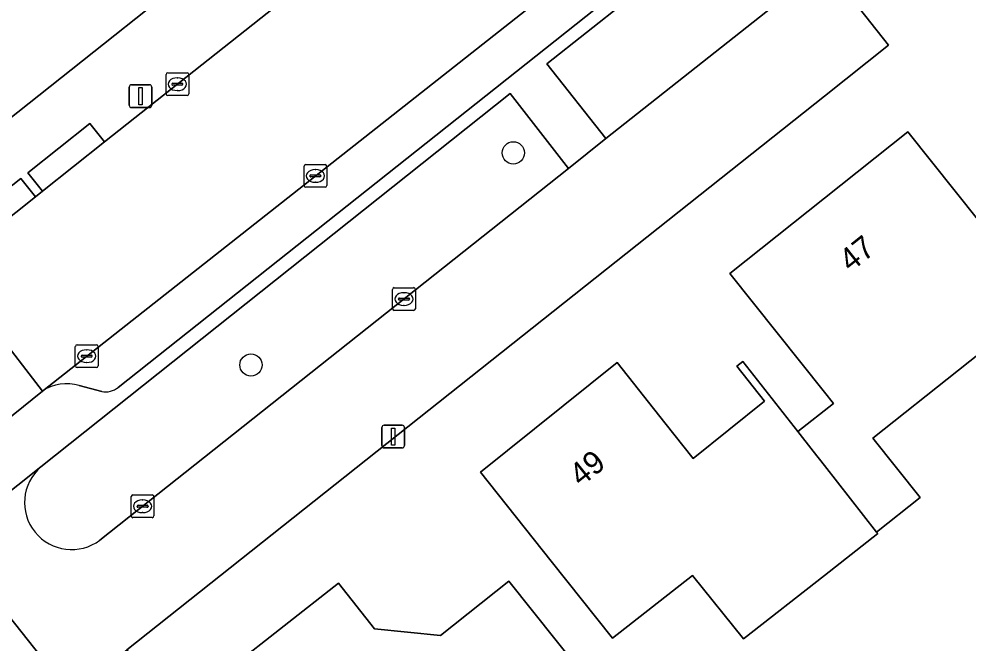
# Model space of a CAD drawing. Extents: x 159499 to 160349, y 382524 to 383273.
# Drawn here: x 159964.6 to 160006.36, y 383112.66 to 383140.09 of the extents above; entities that cross this region are included whole.
import ezdxf

# ---------------------------------------------------------------- set-up
doc = ezdxf.new("R2010")
doc.units = 0
for name, color, linetype in [('IMGEO_Boom', 7, 'Continuous'), ('IMGEO_Erf', 7, 'Continuous'), ('IMGEO_Groenvoorziening', 7, 'Continuous'), ('IMGEO_Kolk', 7, 'Continuous'), ('IMGEO_Lichtmast', 7, 'Continuous'), ('IMGEO_Pand', 7, 'Continuous'), ('IMGEO_Pand_nummerreeks', 7, 'Continuous'), ('IMGEO_Parkeervlak_open', 7, 'Continuous'), ('IMGEO_Rijbaan_lokaal_open', 7, 'Continuous'), ('IMGEO_Voetpad_open', 7, 'Continuous')]:
    doc.layers.add(name, color=color, linetype=linetype)

msp = doc.modelspace()

# ---------------------------------------------------------------- linework, layer by layer
at = {"layer": 'IMGEO_Boom'}
for centre in [(159986.328, 383134.208), (159974.796, 383124.886)]:
    msp.add_circle(centre, 0.489, dxfattribs=at)
at = {"layer": 'IMGEO_Erf'}
for points in [[(159838.776, 383036.162), (160000, 383164.155)], [(160069.07, 383073.156), (160071.919, 383076.914), (160077.006, 383081.993), (160081.991, 383086.829), (160067.75, 383101.08), (160016.301, 383152.744), (160001.274, 383140.9), (160002.826, 383138.938), (160000, 383136.696), (159969.339, 383112.369), (160000, 383073.962), (160006.879, 383065.344), (160051.214, 383033.728), (160053.92, 383031.798), (160060.452, 383040.944)]]:
    msp.add_lwpolyline(points, dxfattribs=at)
for points in [[(160004.209, 383119.058), (160002.296, 383117.538), (160002.349, 383117.471), (160000, 383115.631), (159996.451, 383112.851), (159994.2, 383115.629), (159990.696, 383112.874), (159987.999, 383116.264), (159984.887, 383120.176), (159990.894, 383124.991), (159992.99, 383122.344), (159994.232, 383120.776), (159997.365, 383123.295), (159996.151, 383124.828), (159996.416, 383125.034), (159998.829, 383121.957), (160000.398, 383123.188), (160000, 383123.688), (159995.843, 383128.911), (160000, 383132.215), (160003.671, 383135.132), (160006.794, 383131.227), (160009.659, 383127.643), (160002.137, 383121.666)], [(159990.718, 383109.639), (159985.126, 383105.184), (159985.737, 383104.418), (159986.361, 383104.917), (159987.389, 383103.626), (159986.881, 383103.221), (159982.971, 383100.104), (159980.091, 383103.717), (159980.599, 383104.122), (159978.131, 383107.219), (159977.63, 383106.82), (159973.87, 383111.54), (159978.65, 383115.3), (159980.233, 383113.288), (159983.128, 383112.99), (159986.139, 383115.388), (159989.255, 383111.477)]]:
    msp.add_lwpolyline(points, close=True, dxfattribs=at)
at = {"layer": 'IMGEO_Groenvoorziening'}
for points in [[(160009.287, 383155.131), (160000, 383147.78), (159987.796, 383138.118), (159990.398, 383134.835), (160000, 383142.448), (160012.044, 383151.997)], [(159988.759, 383133.521), (159986.191, 383136.82), (159965.56, 383120.401)], [(159968.16, 383117.19), (159988.759, 383133.521)]]:
    msp.add_lwpolyline(points, dxfattribs=at)
msp.add_arc((159966.913, 383118.839), 2.067, 130.8921, 307.1032, dxfattribs=at)
at = {"layer": 'IMGEO_Kolk'}
for p, q in [((159971.064, 383136.801), (159971.064, 383137.653)), ((159971.139, 383137.727), (159971.991, 383137.727)), ((159971.552, 383137.507), (159971.577, 383137.507)), ((159972.065, 383137.653), (159972.065, 383136.801)), ((159971.323, 383137.221), (159971.323, 383137.233)), ((159971.761, 383137.184), (159971.363, 383137.184)), ((159971.366, 383137.27), (159971.764, 383137.27)), ((159971.807, 383137.233), (159971.807, 383137.221)), ((159971.991, 383136.727), (159971.139, 383136.727)), ((159971.575, 383136.947), (159971.55, 383136.947)), ((159977.206, 383133.696), (159978.058, 383133.696)), ((159977.131, 383132.77), (159977.131, 383133.622)), ((159977.433, 383133.239), (159977.831, 383133.239)), ((159977.619, 383133.476), (159977.644, 383133.476)), ((159978.132, 383133.622), (159978.132, 383132.77)), ((159977.39, 383133.19), (159977.39, 383133.202)), ((159977.828, 383133.153), (159977.43, 383133.153)), ((159977.642, 383132.916), (159977.617, 383132.916)), ((159977.874, 383133.202), (159977.874, 383133.19)), ((159978.058, 383132.696), (159977.206, 383132.696)), ((159981.022, 383127.357), (159981.022, 383128.209)), ((159981.097, 383128.283), (159981.949, 383128.283)), ((159982.023, 383128.209), (159982.023, 383127.357)), ((159981.324, 383127.826), (159981.722, 383127.826)), ((159981.51, 383128.063), (159981.535, 383128.063)), ((159981.281, 383127.777), (159981.281, 383127.789)), ((159981.719, 383127.74), (159981.321, 383127.74)), ((159981.533, 383127.503), (159981.508, 383127.503)), ((159981.765, 383127.789), (159981.765, 383127.777)), ((159981.949, 383127.283), (159981.097, 383127.283)), ((159967.153, 383125.773), (159968.005, 383125.773)), ((159967.078, 383124.847), (159967.078, 383125.699)), ((159967.38, 383125.316), (159967.778, 383125.316)), ((159967.566, 383125.553), (159967.591, 383125.553)), ((159968.079, 383125.699), (159968.079, 383124.847)), ((159967.337, 383125.267), (159967.337, 383125.279)), ((159967.775, 383125.23), (159967.377, 383125.23)), ((159967.589, 383124.993), (159967.564, 383124.993)), ((159967.821, 383125.279), (159967.821, 383125.267)), ((159968.005, 383124.773), (159967.153, 383124.773)), ((159969.532, 383118.248), (159969.532, 383119.1)), ((159969.607, 383119.174), (159970.459, 383119.174)), ((159970.533, 383119.1), (159970.533, 383118.248)), ((159969.791, 383118.668), (159969.791, 383118.68)), ((159970.229, 383118.631), (159969.831, 383118.631)), ((159969.834, 383118.717), (159970.232, 383118.717)), ((159970.02, 383118.954), (159970.045, 383118.954)), ((159970.275, 383118.68), (159970.275, 383118.668)), ((159970.043, 383118.394), (159970.018, 383118.394)), ((159970.459, 383118.174), (159969.607, 383118.174))]:
    msp.add_line(p, q, dxfattribs=at)
for points in [[(159971.064, 383136.801), (159971.064, 383137.653)], [(159971.139, 383137.727), (159971.991, 383137.727)], [(159972.065, 383137.653), (159972.065, 383136.801)], [(159971.991, 383136.727), (159971.139, 383136.727)], [(159977.206, 383133.696), (159978.058, 383133.696)], [(159977.131, 383132.77), (159977.131, 383133.622)], [(159978.132, 383133.622), (159978.132, 383132.77)], [(159978.058, 383132.696), (159977.206, 383132.696)], [(159981.022, 383127.357), (159981.022, 383128.209)], [(159981.097, 383128.283), (159981.949, 383128.283)], [(159982.023, 383128.209), (159982.023, 383127.357)], [(159981.949, 383127.283), (159981.097, 383127.283)], [(159967.153, 383125.773), (159968.005, 383125.773)], [(159967.078, 383124.847), (159967.078, 383125.699)], [(159968.079, 383125.699), (159968.079, 383124.847)], [(159968.005, 383124.773), (159967.153, 383124.773)], [(159969.532, 383118.248), (159969.532, 383119.1)], [(159969.607, 383119.174), (159970.459, 383119.174)], [(159970.533, 383119.1), (159970.533, 383118.248)], [(159970.459, 383118.174), (159969.607, 383118.174)]]:
    msp.add_lwpolyline(points, dxfattribs=at)
for centre, radius, start, end in [((159971.141, 383137.651), 0.0765, 91.552, 178.448), ((159971.141, 383137.651), 0.0765, 91.552, 178.448), ((159971.989, 383137.651), 0.0765, 1.552, 88.448), ((159971.989, 383137.651), 0.0765, 1.552, 88.448), ((159971.363, 383137.23), 0.0403, 85.8775, 175.7526), ((159971.36, 383137.22), 0.0366, 178.938, 274.7102), ((159971.764, 383137.227), 0.043, 264.8664, 352.4533), ((159971.768, 383137.232), 0.0386, 1.7309, 96.639), ((159971.141, 383136.803), 0.0765, 181.552, 268.448), ((159971.141, 383136.803), 0.0765, 181.552, 268.448), ((159971.989, 383136.803), 0.0765, 271.552, 358.448), ((159971.989, 383136.803), 0.0765, 271.552, 358.448), ((159977.208, 383133.62), 0.0765, 91.552, 178.448), ((159977.208, 383133.62), 0.0765, 91.552, 178.448), ((159978.056, 383133.62), 0.0765, 1.552, 88.448), ((159978.056, 383133.62), 0.0765, 1.552, 88.448), ((159977.43, 383133.199), 0.0403, 85.8775, 175.7526), ((159977.835, 383133.201), 0.0386, 1.7309, 96.639), ((159977.427, 383133.189), 0.0366, 178.938, 274.7102), ((159977.831, 383133.196), 0.043, 264.8664, 352.4533), ((159977.208, 383132.772), 0.0765, 181.552, 268.448), ((159977.208, 383132.772), 0.0765, 181.552, 268.448), ((159978.056, 383132.772), 0.0765, 271.552, 358.448), ((159978.056, 383132.772), 0.0765, 271.552, 358.448), ((159981.099, 383128.207), 0.0765, 91.552, 178.448), ((159981.099, 383128.207), 0.0765, 91.552, 178.448), ((159981.947, 383128.207), 0.0765, 1.552, 88.448), ((159981.947, 383128.207), 0.0765, 1.552, 88.448), ((159981.321, 383127.786), 0.0403, 85.8775, 175.7526), ((159981.726, 383127.788), 0.0386, 1.7309, 96.639), ((159981.318, 383127.776), 0.0366, 178.938, 274.7102), ((159981.722, 383127.783), 0.043, 264.8664, 352.4533), ((159981.099, 383127.359), 0.0765, 181.552, 268.448), ((159981.099, 383127.359), 0.0765, 181.552, 268.448), ((159981.947, 383127.359), 0.0765, 271.552, 358.448), ((159981.947, 383127.359), 0.0765, 271.552, 358.448), ((159967.155, 383125.697), 0.0765, 91.552, 178.448), ((159967.155, 383125.697), 0.0765, 91.552, 178.448), ((159968.003, 383125.697), 0.0765, 1.552, 88.448), ((159968.003, 383125.697), 0.0765, 1.552, 88.448), ((159967.377, 383125.276), 0.0403, 85.8775, 175.7526), ((159967.782, 383125.278), 0.0386, 1.7309, 96.639), ((159967.374, 383125.266), 0.0366, 178.938, 274.7102), ((159967.778, 383125.273), 0.043, 264.8664, 352.4533), ((159967.155, 383124.849), 0.0765, 181.552, 268.448), ((159967.155, 383124.849), 0.0765, 181.552, 268.448), ((159968.003, 383124.849), 0.0765, 271.552, 358.448), ((159968.003, 383124.849), 0.0765, 271.552, 358.448), ((159969.609, 383119.098), 0.0765, 91.552, 178.448), ((159969.609, 383119.098), 0.0765, 91.552, 178.448), ((159970.457, 383119.098), 0.0765, 1.552, 88.448), ((159970.457, 383119.098), 0.0765, 1.552, 88.448), ((159969.831, 383118.677), 0.0403, 85.8775, 175.7526), ((159969.828, 383118.667), 0.0366, 178.938, 274.7102), ((159970.232, 383118.674), 0.043, 264.8664, 352.4533), ((159970.236, 383118.679), 0.0386, 1.7309, 96.639), ((159969.609, 383118.25), 0.0765, 181.552, 268.448), ((159969.609, 383118.25), 0.0765, 181.552, 268.448), ((159970.457, 383118.25), 0.0765, 271.552, 358.448), ((159970.457, 383118.25), 0.0765, 271.552, 358.448)]:
    msp.add_arc(centre, radius, start, end, dxfattribs=at)
for centre, major_axis, ratio, start_param, end_param in [((159971.551, 383137.227), (-0.387, 0.002), 0.722429, 4.712389, 7.853982), ((159971.576, 383137.227), (-0.39, 0.002), 0.717154, 1.570796, 4.712389), ((159977.618, 383133.196), (-0.387, 0.002), 0.722429, 4.712389, 7.853982), ((159977.643, 383133.196), (-0.39, 0.002), 0.717154, 1.570796, 4.712389), ((159981.509, 383127.783), (-0.387, 0.002), 0.722429, 4.712389, 7.853982), ((159981.534, 383127.783), (-0.39, 0.002), 0.717154, 1.570796, 4.712389), ((159967.565, 383125.273), (-0.387, 0.002), 0.722429, 4.712389, 7.853982), ((159967.59, 383125.273), (-0.39, 0.002), 0.717154, 1.570796, 4.712389), ((159970.019, 383118.674), (-0.387, 0.002), 0.722429, 4.712389, 7.853982), ((159970.044, 383118.674), (-0.39, 0.002), 0.717154, 1.570796, 4.712389)]:
    msp.add_ellipse(centre, major_axis=major_axis, ratio=ratio, start_param=start_param, end_param=end_param, dxfattribs=at)
at = {"layer": 'IMGEO_Lichtmast'}
for p, q in [((159969.45, 383136.3), (159969.45, 383137.1)), ((159969.45, 383137.1), (159969.45, 383136.3)), ((159969.55, 383137.2), (159970.34, 383137.2)), ((159970.34, 383137.2), (159969.55, 383137.2)), ((159970.44, 383137.1), (159970.44, 383136.3)), ((159970.44, 383136.3), (159970.44, 383137.1)), ((159970.34, 383136.2), (159969.55, 383136.2)), ((159969.55, 383136.2), (159970.34, 383136.2)), ((159980.555, 383121.339), (159980.555, 383122.139)), ((159980.555, 383122.139), (159980.555, 383121.339)), ((159980.655, 383122.239), (159981.445, 383122.239)), ((159981.445, 383122.239), (159980.655, 383122.239)), ((159981.545, 383122.139), (159981.545, 383121.339)), ((159981.545, 383121.339), (159981.545, 383122.139)), ((159981.445, 383121.239), (159980.655, 383121.239)), ((159980.655, 383121.239), (159981.445, 383121.239))]:
    msp.add_line(p, q, dxfattribs=at)
for points in [[(159969.87, 383137.075), (159970.02, 383137.075), (159970.02, 383136.325), (159969.87, 383136.325), (159969.87, 383137.075)], [(159980.975, 383122.114), (159981.125, 383122.114), (159981.125, 383121.364), (159980.975, 383121.364), (159980.975, 383122.114)]]:
    msp.add_lwpolyline(points, dxfattribs=at)
for centre, start, end in [((159969.55, 383137.1), 90, 180), ((159969.55, 383137.1), 90, 180), ((159970.34, 383137.1), 0, 90), ((159970.34, 383137.1), 360, 90), ((159969.55, 383136.3), 180, 270), ((159969.55, 383136.3), 180, 270), ((159970.34, 383136.3), 270, 0), ((159970.34, 383136.3), 270, 0), ((159980.655, 383122.139), 90, 180), ((159980.655, 383122.139), 90, 180), ((159981.445, 383122.139), 0, 90), ((159981.445, 383122.139), 360, 90), ((159980.655, 383121.339), 180, 270), ((159980.655, 383121.339), 180, 270), ((159981.445, 383121.339), 270, 0), ((159981.445, 383121.339), 270, 0)]:
    msp.add_arc(centre, 0.1, start, end, dxfattribs=at)
at = {"layer": 'IMGEO_Pand'}
for points in [[(160006.794, 383131.227), (160003.671, 383135.132), (160000, 383132.215), (159995.843, 383128.911), (160000, 383123.688), (160000.398, 383123.188), (159998.829, 383121.957), (159999.502, 383121.1), (160000, 383120.466), (160002.296, 383117.538), (160004.209, 383119.058), (160002.137, 383121.666), (160009.659, 383127.643)], [(160000, 383120.466), (159999.502, 383121.1), (159998.829, 383121.957), (159996.416, 383125.034), (159996.151, 383124.828), (159997.365, 383123.295), (159994.232, 383120.776), (159992.99, 383122.344), (159990.894, 383124.991), (159984.887, 383120.176), (159987.999, 383116.264), (159990.696, 383112.874), (159994.2, 383115.629), (159996.451, 383112.851), (160000, 383115.631), (160002.349, 383117.471), (160002.296, 383117.538)], [(159989.255, 383111.477), (159986.139, 383115.388), (159983.128, 383112.99), (159980.233, 383113.288), (159978.65, 383115.3), (159973.87, 383111.54), (159977.63, 383106.82), (159978.131, 383107.219), (159980.599, 383104.122), (159980.091, 383103.717), (159982.971, 383100.104), (159986.881, 383103.221), (159987.389, 383103.626), (159986.361, 383104.917), (159985.737, 383104.418), (159985.126, 383105.184), (159990.718, 383109.639)]]:
    msp.add_lwpolyline(points, close=True, dxfattribs=at)
at = {"layer": 'IMGEO_Parkeervlak_open'}
for points in [[(160005.521, 383155.177), (159965.635, 383123.738)], [(159968.962, 383123.902), (160000, 383148.54), (160004.48, 383152.096)], [(159967.244, 383123.978), (159968.239, 383123.717)]]:
    msp.add_lwpolyline(points, dxfattribs=at)
for centre, radius, start, end in [((159966.693, 383122.161), 1.898, 73.1147, 123.8528), ((159968.4, 383124.591), 0.889, 259.5356, 309.17)]:
    msp.add_arc(centre, radius, start, end, dxfattribs=at)
at = {"layer": 'IMGEO_Rijbaan_lokaal_open'}
for points in [[(160007.337, 383165.518), (159985.41, 383148.209), (159982.548, 383145.937), (159982.197, 383145.658), (159979.79, 383143.748), (159968.366, 383134.687), (159965.633, 383132.52), (159965.323, 383132.274), (159962.64, 383130.146), (159961.424, 383129.181), (159965.635, 383123.738), (160005.521, 383155.177), (160009.599, 383158.345)], [(160000, 383136.696), (160002.826, 383138.938), (160001.274, 383140.9), (160000, 383142.448), (159990.398, 383134.835), (159988.759, 383133.521), (159968.16, 383117.19)], [(159965.56, 383120.401), (159961.505, 383117.191), (159966.858, 383110.439), (159969.339, 383112.369), (160000, 383136.696)], [(160000, 383068.637), (159989.829, 383081.465), (159986.263, 383085.963), (159980.273, 383093.518), (159973.467, 383102.103), (159966.858, 383110.439), (159961.505, 383117.191), (159957.5, 383114.019), (159962.836, 383107.311), (159995.46, 383066.299)]]:
    msp.add_lwpolyline(points, dxfattribs=at)
msp.add_lwpolyline([(159965.635, 383123.738), (159961.424, 383129.181), (159959.2, 383127.414), (159963.491, 383122.013)], close=True, dxfattribs=at)
msp.add_arc((159966.913, 383118.839), 2.067, 130.8921, 307.1032, dxfattribs=at)
at = {"layer": 'IMGEO_Voetpad_open'}
for points in [[(159961.994, 383130.961), (159964.677, 383133.089), (159965.323, 383132.274), (159965.633, 383132.52), (159964.987, 383133.335), (159967.72, 383135.502), (159968.366, 383134.687), (159979.79, 383143.748), (159979.144, 383144.563), (159981.551, 383146.473), (159982.197, 383145.658), (159982.548, 383145.937), (159981.901, 383146.752), (159984.763, 383149.024), (159985.41, 383148.209), (160007.337, 383165.518), (160004.812, 383170.397)], [(160003.86, 383167.245), (160000, 383164.155), (159838.776, 383036.162), (159834.352, 383032.405), (159830.825, 383029.654), (159830.707, 383026.63), (159837.797, 383032.248), (159838.443, 383031.433), (159841.883, 383034.159), (159859.981, 383048.564)], [(159986.191, 383136.82), (159988.759, 383133.521), (159990.398, 383134.835), (159987.796, 383138.118), (160000, 383147.78), (160009.287, 383155.131)], [(160004.48, 383152.096), (160000, 383148.54), (159968.962, 383123.902)], [(159965.635, 383123.738), (159963.491, 383122.013), (159962.358, 383121.1), (159962.671, 383120.711), (159955.072, 383114.583), (159957.5, 383114.019), (159961.505, 383117.191), (159965.56, 383120.401), (159986.191, 383136.82)], [(159968.239, 383123.717), (159967.244, 383123.978)]]:
    msp.add_lwpolyline(points, dxfattribs=at)
for points in [[(159965.633, 383132.52), (159968.366, 383134.687), (159967.72, 383135.502), (159964.987, 383133.335)], [(159965.323, 383132.274), (159964.677, 383133.089), (159961.994, 383130.961), (159962.64, 383130.146)]]:
    msp.add_lwpolyline(points, close=True, dxfattribs=at)
for centre, radius, start, end in [((159966.693, 383122.161), 1.898, 73.1147, 123.8528), ((159968.4, 383124.591), 0.889, 259.5356, 309.17)]:
    msp.add_arc(centre, radius, start, end, dxfattribs=at)

# ---------------------------------------------------------------- texts
at = {"layer": 'IMGEO_Pand_nummerreeks'}
for s, rotation, p in [('47', 38.4741, (160001.151, 383128.94)), ('49', 38.7148, (159989.298, 383119.508))]:
    msp.add_text(s, height=1, rotation=rotation, dxfattribs=at).set_placement(p)

doc.saveas('drawing.dxf')
